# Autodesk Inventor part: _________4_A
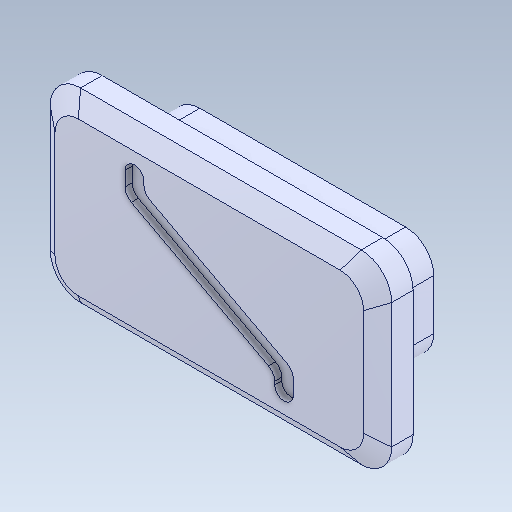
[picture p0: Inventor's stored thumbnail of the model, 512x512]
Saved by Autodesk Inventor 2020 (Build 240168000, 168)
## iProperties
Created: 2017-09
Part Number: _________4_A
Material: Générique
Document SubType Name: Modeling
Designer: bruno
Density: 1 g/cm^3
Appearance: Par défaut
Author: bruno
Sending System: SolidWorks 2016
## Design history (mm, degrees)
feature "Importée1"
node "Solide1"
